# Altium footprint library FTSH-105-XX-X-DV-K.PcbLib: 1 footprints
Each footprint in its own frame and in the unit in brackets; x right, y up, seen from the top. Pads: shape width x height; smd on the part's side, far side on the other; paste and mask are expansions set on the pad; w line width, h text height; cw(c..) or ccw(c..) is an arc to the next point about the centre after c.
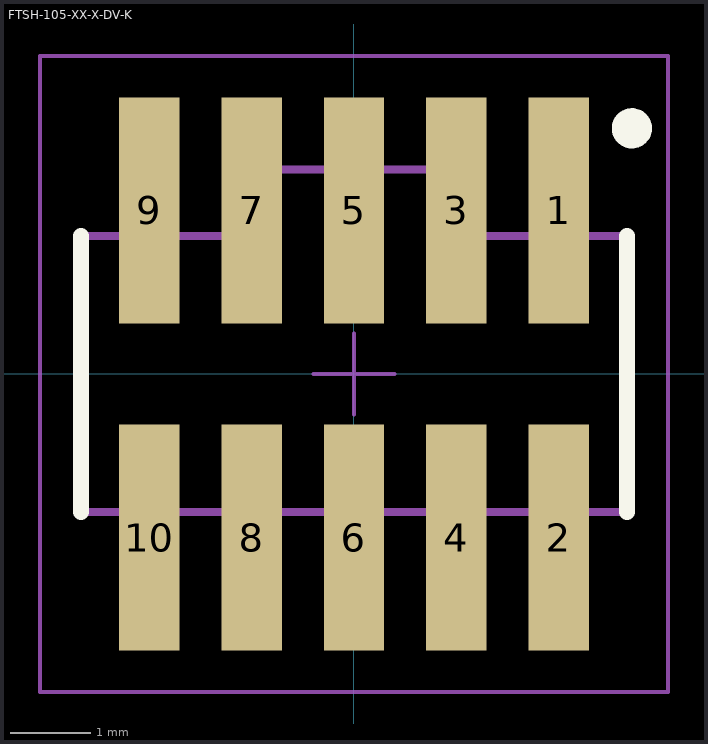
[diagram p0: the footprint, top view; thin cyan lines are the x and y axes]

## FTSH-105-XX-X-DV-K [mm] "1.27mm pitch, 10 pin, terminal strip; keyed"
height 5.97
pads (10):
  rect 0.75x2.8 smd mask+0: 1(2.54,2.03) 2(2.54,-2.03) 3(1.27,2.03) 4(1.27,-2.03) 5(0,2.03) 6(0,-2.03) 7(-1.27,2.03) 8(-1.27,-2.03) 9(-2.54,2.03) 10(-2.54,-2.03)
Top Overlay:
  circle w0.25: c3.45,3.05 r0.125
  lines w0.2: -3.391,-1.715 -3.391,1.715 ; 3.391,-1.715 3.391,1.715
Mechanical 12:
  lines w0.001: -3.391,-1.715 -3.391,1.715 -1.08,1.715 -1.08,2.54 1.08,2.54 1.08,1.715 3.384,1.715 3.391,1.708 3.391,-1.715 -3.391,-1.715
Mechanical 13:
  lines w0.1: -3.391,-1.708 -3.384,-1.715 ; 3.384,1.715 1.08,1.715 1.08,2.54 -1.08,2.54 -1.08,1.715 -3.391,1.715 -3.391,-1.715 3.391,-1.715 3.391,1.708
  text ".Designator" at 0.254,0.254 h1.52
Mechanical 15:
  lines w0.05: -0.5,0 0.5,0 ; 0,-0.5 0,0.5 ; -3.9,-3.95 -3.9,3.95 3.9,3.95 3.9,-3.95 -3.9,-3.95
